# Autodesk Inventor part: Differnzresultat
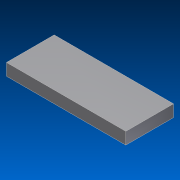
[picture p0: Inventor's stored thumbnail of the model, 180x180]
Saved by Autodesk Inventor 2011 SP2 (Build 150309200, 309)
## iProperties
Created: 2012-03
Part Number: Differnzresultat
Document SubType Name: Modeling
Designer: BH
Density: 1 g/cm^3
Author: BH
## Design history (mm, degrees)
sketch "Skizze1"
  geometry: L1 (0, 0)-(100, 0); L2 (100, 0)-(100, -40); L3 (100, -40)-(0, -40); L4 (0, -40)-(0, 0)
  constraints: 8 end point, 2 parallel, 1 horizontal, 1 perpendicular
  dimensions: "d0" = 100 distance of L2.end L3.end; "d1" = 40 distance of L1.end L2.end
extrude "Extrusion1" new body sketch "Skizze1" distance "d2" = 10; taper "d3" = 0 deg
node "Volumenkörper1"
